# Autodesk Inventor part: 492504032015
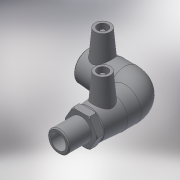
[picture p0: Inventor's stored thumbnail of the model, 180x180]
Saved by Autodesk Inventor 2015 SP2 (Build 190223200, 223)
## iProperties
Created: 2017-06
Part Number: 492504032015
Material: Generic
Description: PLASSON 90° ELBOW MALE TRANSITION 32-1.1/2"
Document SubType Name: Modeling
Designer: KIM
Mass: 140.239 g
Surface Area: 427.999 cm^2
Volume: 140.239 cm^3
Density: 1 g/cm^3
Appearance: Default
Author: KIM
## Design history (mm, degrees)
derived "492504.ipt"
feature "Solid1::492504.ipt"
tag "TaggingFeature1"
body "Solid1"
other parameters: "d2" = 44, "d4" = 27.66667, "d5" = 39.6, "d8" = 168 deg, "d10" = 16, "d11" = 5.33333, "d29" = 43, "d30" = 15, "d31" = 45.65, "d34" = 5 deg, "d41" = 4, "d42" = 14, "d43" = 0, "d48" = 61, "d49" = 32, "d50" = 27.2, "d51" = 16, "d54" = 90 deg, "d57" = 32, "d59" = 0, "d61" = 90 deg, "d86" = 3, "d87" = 0, "d93" = 0.1, "d94" = 9, "d95" = 47.803, "d96" = 33.4621, "d97" = 23, "d98" = 36, "d99" = 57.2, "d100" = 32.4, "d102" = 1.6, "d106" = 0, "d_" = 32, "L_" = 119, "D_" = 23, "A_" = 43, "d_2" = 12, "L_2" = 36, "D_1" = 44, "R_" = 47.803
